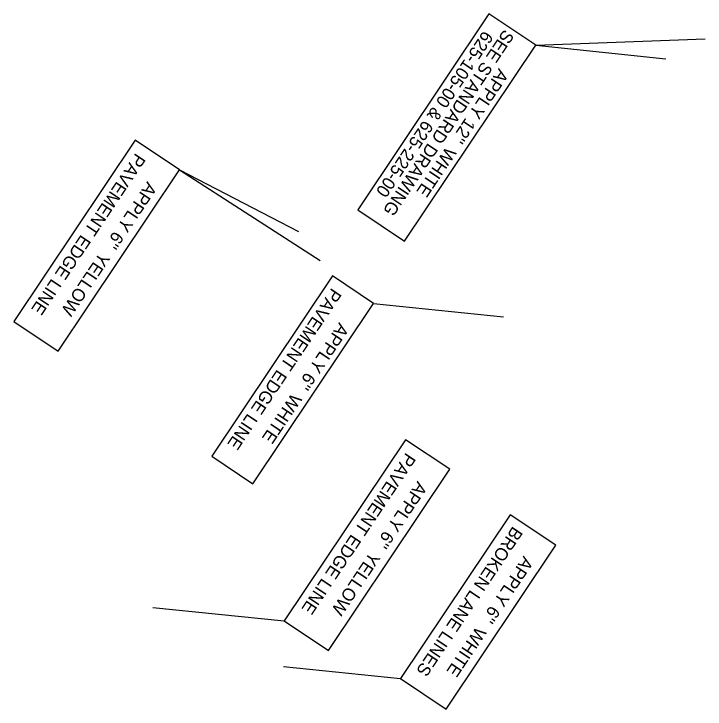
# Model space of a CAD drawing. Extents: x 1966013 to 1974896, y 789499 to 804826.
# Drawn here: x 1972314.5 to 1972749.8, y 797389.5 to 797827.3 of the extents above; entities that cross this region are included whole.
import ezdxf

# ---------------------------------------------------------------- set-up
doc = ezdxf.new("R2010")
doc.units = 0
doc.layers.add('RD_EX_H2O_BlueLn', color=7, linetype='Continuous')

msp = doc.modelspace()

# ---------------------------------------------------------------- linework, layer by layer
at = {"layer": 'RD_EX_H2O_BlueLn'}
for p, q in [((1972643.23, 797807.55), (1972749.79, 797811.56)), ((1972643.23, 797807.55), (1972725.04, 797799.1)), ((1972418.8, 797729.15), (1972493.73, 797690.39)), ((1972418.8, 797729.15), (1972507.36, 797671.94)), ((1972541.09, 797644.95), (1972622.9, 797636.5)), ((1972401.97, 797453.58), (1972484.74, 797445.03)), ((1972484.29, 797416.4), (1972557.93, 797408.79))]:
    msp.add_line(p, q, dxfattribs=at)
for points in [[(1972613.7, 797827.33), (1972531.04, 797703.9), (1972560.58, 797684.12), (1972643.23, 797807.55)], [(1972390.97, 797747.79), (1972314.55, 797633.66), (1972342.38, 797615.03), (1972418.8, 797729.15)], [(1972515.2, 797662.29), (1972439.14, 797548.71), (1972465.03, 797531.37), (1972541.09, 797644.95)], [(1972561.17, 797559.16), (1972484.74, 797445.03), (1972512.57, 797426.4), (1972588.99, 797540.52)], [(1972627.02, 797511.96), (1972557.93, 797408.79), (1972586.71, 797389.52), (1972655.8, 797492.68)]]:
    msp.add_lwpolyline(points, close=True, dxfattribs=at)

# ---------------------------------------------------------------- texts
for s, height, rotation, p in [('625-105-00 & 625-225-00', 7.9995, 236.1914, (1972610.32, 797817.2)), ('SEE STANDARD DRAWING', 7.9995, 236.1914, (1972623.36, 797818.08)), ("APPLY 12''  WHITE", 7.9996, 236.1914, (1972619.91, 797793.47)), ('PAVEMENT EDGE LINE', 7.9995, 236.1914, (1972391.29, 797740.1)), ("APPLY 6''  YELLOW", 7.9996, 236.1914, (1972398.51, 797722.13)), ('PAVEMENT EDGE LINE', 7.9995, 236.1914, (1972514.75, 797655.18)), ("APPLY 6''  WHITE", 7.9996, 236.1914, (1972519.37, 797633.32)), ('PAVEMENT EDGE LINE', 7.9995, 236.1914, (1972561.48, 797551.47)), ("APPLY 6''  YELLOW", 7.9996, 236.1914, (1972568.71, 797533.5)), ('BROKEN LANE LINES', 8.0004, 236.1913, (1972628.81, 797505.1)), ("APPLY 6''  WHITE", 7.9995, 236.1913, (1972635.53, 797486.36))]:
    msp.add_text(s, height=height, rotation=rotation, dxfattribs=at).set_placement(p)

doc.saveas('drawing.dxf')
